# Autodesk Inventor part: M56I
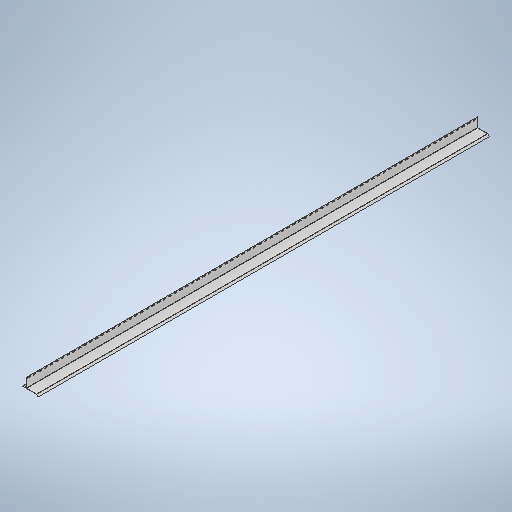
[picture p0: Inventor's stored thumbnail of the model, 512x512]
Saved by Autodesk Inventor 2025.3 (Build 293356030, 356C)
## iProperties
Created: 2024-06
Part Number: M56I
Material: Generic
Document SubType Name: Modeling
Designer: mathieu.gyimah-chias
Density: 1 g/cm^3
Appearance: Default
Author: mathieu.gyimah-chias
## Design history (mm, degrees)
sketch "Sketch1"
  geometry: L1 (-38.137, -22.666)-(29.49, -22.678); L2 (-38.761, 40.326)-(-38.772, -22.031); L3 (-39.269, 40.326)-(-38.761, 40.326); L4 (-39.28, -22.031)-(-39.269, 40.326); L5 (29.49, -23.186)-(-38.137, -23.174); L6 (41.206, -34.327)-(30.478, -23.596); L7 (30.225, -23.845)-(40.955, -34.579); L8 (-64.001, -23.513)-(29.462, -23.529); L9 (-51.98, -23.172)-(-64.001, -23.17); L10 (-51.98, -22.664)-(-51.98, -23.172); L11 (-64.001, -22.662)-(-51.98, -22.664); L12 (29.462, -24.037)-(-64.001, -24.021); L13 (40.595, -34.938)-(29.866, -24.205); L14 (30.837, -23.236)-(41.565, -33.968); A1 r 1.905 centre (29.49, -24.583) between (30.837, -23.236) and (29.49, -22.678); A2 r 0.635 centre (-38.137, -22.031) between (-38.772, -22.031) and (-38.137, -22.666); A3 r 1.143 centre (-38.137, -22.031) between (-39.28, -22.031) and (-38.137, -23.174); A4 r 1.397 centre (29.49, -24.583) between (30.478, -23.596) and (29.49, -23.186); A5 r 0.178 centre (41.08, -34.453) between (40.955, -34.579) and (41.206, -34.327); A6 r 1.079 centre (29.461, -24.609) between (30.225, -23.845) and (29.462, -23.529); A7 r 0.171 centre (-64.001, -23.341) between (-64.001, -23.17) and (-64.001, -23.513); A8 r 0.679 centre (-64.001, -23.341) between (-64.001, -22.662) and (-64.001, -24.021); A9 r 0.571 centre (29.461, -24.609) between (29.866, -24.205) and (29.462, -24.037); A10 r 0.686 centre (41.08, -34.453) between (40.595, -34.938) and (41.565, -33.968); 4 further points
  constraints: 28 end point, 22 point on circle, 20 tangent, 10 centre point, 9 parallel, 3 perpendicular
  dimensions: "d0" = 0.508 distance between parallel lines of L2 L4; "d1" = 0.508 distance between parallel lines of L5 L1; "d2" = 0.508 distance between parallel lines of L14 L6; "d3" = 0.508 distance between parallel lines of L13 L7; "d4" = 0.508 distance between parallel lines of L12 L8; "d5" = 0.508 distance between parallel lines of L11 L9; "d6" = 0.3429 distance between parallel lines of L8 L5; "d7" = 135 deg angle of L14 L1; "d9" = 0.3429 distance between parallel lines of L8 L9; "d10" = 0 distance of A3.centre A2.centre; "d11" = 0 distance of A4.centre A1.centre; "d12" = 0 distance of A6.centre A9.centre; "d13" = 0 distance of A7.centre A8.centre; "d14" = 1.143 radius of A3; "d15" = 1.905 radius of A1; "d18" = 25.4 distance from line of L4 point (-64.68, -23.341); "d19" = 12.7 distance from line of L10 point (-64.68, -23.341); "d20" = 63.5 distance between parallel lines of L3 L5; "d21" = 68.2625 distance from line of L2 L1.end; "d28" = 0.6858 radius of A10; "d29" = 15.875 distance of point (41.565, -34.938) L14.start
extrude "Extrusion1" new body sketch "Sketch1" distance "d23" = 3048; taper "d24" = 0 deg
sketch "Sketch2"
  geometry: L1 (25.006, 56.007)-(9.919, 56.007); L2 (9.919, 52.045)-(25.006, 52.045); L3 (0, 62.357)-(3048, 62.357) reference; L4 (0, 0)-(0, 62.357) reference; A1 r 1.981 centre (9.919, 54.026) between (9.919, 56.007) and (9.919, 52.045); A2 r 1.981 centre (25.006, 54.026) between (25.006, 52.045) and (25.006, 56.007); 3 further points
  constraints: 6 point on circle, 4 end point, 4 tangent, 2 centre point, 2 horizontal
  dimensions: "d30" = 6.35 distance between parallel lines of L3 L1; "d31" = 3.9624 distance between parallel lines of L1 L2; "d32" = 7.9375 distance from line of L4 point (7.938, 54.026); "d33" = 19.05 distance of point (26.988, 54.026) point (7.938, 54.026)
extrude "Extrusion2" cut sketch "Sketch2" distance "d34" = 25.4; taper "d35" = 0 deg
body "Solid1"
pattern_linear "Rectangular Pattern1" dims "d38" = 38.1
